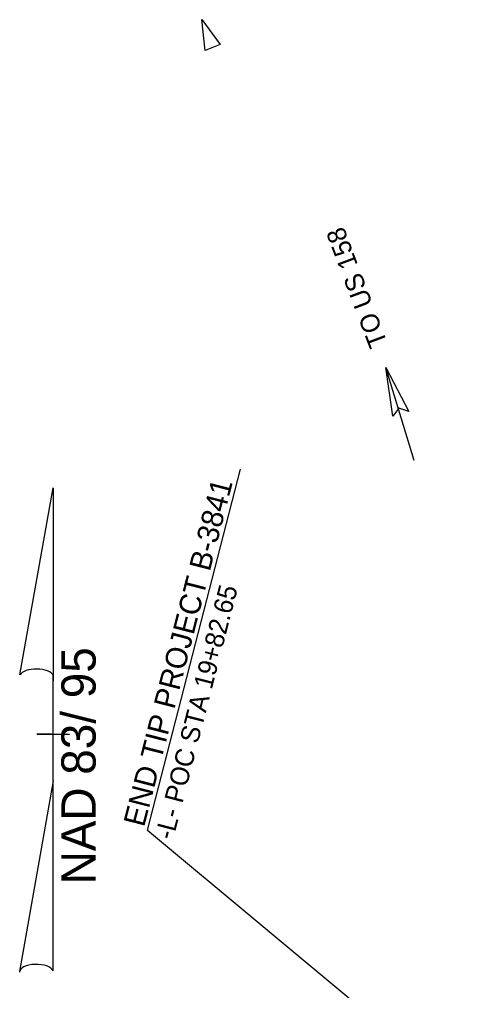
# Model space of a CAD drawing. Extents: x 2078889 to 2079501, y 925860 to 927219.
# Drawn here: x 2079231.9 to 2079401.1, y 926858.4 to 927219.4 of the extents above; entities that cross this region are included whole.
import ezdxf

# ---------------------------------------------------------------- set-up
doc = ezdxf.new("R2010")
doc.units = 0
for name, color, linetype in [('Default', 7, 'Continuous'), ('Prop Horizontal Alignment Curve and Spiral Data', 7, 'Continuous'), ('Prop Horizontal Alignment Direction Label', 7, 'Continuous'), ('Prop Horizontal Alignment Station Label', 7, 'Continuous'), ('Prop North Arrow NAD83 for Plan Sheets CELL', 7, 'Continuous'), ('Prop Terminator CELL', 7, 'Continuous')]:
    doc.layers.add(name, color=color, linetype=linetype)

msp = doc.modelspace()

# ---------------------------------------------------------------- linework, layer by layer
at = {"layer": 'Default'}
msp.add_lwpolyline([(2079300.92, 927207.92), (2079299.72, 927219.42), (2079306.51, 927210.06)], close=True, dxfattribs=at)
at = {"layer": 'Prop Horizontal Alignment Curve and Spiral Data'}
msp.add_line((2079279.57, 926918.1), (2079314.07, 927052.27), dxfattribs=at)
at = {"layer": 'Prop Horizontal Alignment Direction Label'}
msp.add_line((2079378.67, 927055.43), (2079368.16, 927090), dxfattribs=at)
at = {"layer": 'Prop Horizontal Alignment Station Label'}
msp.add_line((2079279.57, 926918.1), (2079401.11, 926816.87), dxfattribs=at)
at = {"layer": 'Prop North Arrow NAD83 for Plan Sheets CELL'}
for p, q in [((2079232.09, 926975.77), (2079244.41, 927045.29)), ((2079244.49, 927045.29), (2079244.41, 927045.29)), ((2079244.49, 927045.29), (2079244.41, 927045.29)), ((2079244.49, 927045.29), (2079244.47, 926973.59)), ((2079244.46, 926936.39), (2079244.47, 926975.69)), ((2079244.47, 926973.59), (2079244.47, 926975.62)), ((2079238.46, 926953.8), (2079238.39, 926953.8)), ((2079243.79, 926953.79), (2079238.46, 926953.8)), ((2079238.54, 926953.8), (2079250.54, 926953.79)), ((2079244.46, 926936.39), (2079231.91, 926865.52)), ((2079244.51, 926865.82), (2079244.46, 926936.39))]:
    msp.add_line(p, q, dxfattribs=at)
for centre, start_param, end_param in [((2079238.3, 926975.03), 0.216388, 2.908219), ((2079238.27, 926865.27), 0.201328, 3.141593)]:
    msp.add_ellipse(centre, major_axis=(6.34, -0.05), ratio=0.461098, start_param=start_param, end_param=end_param, dxfattribs=at)
at = {"layer": 'Prop Terminator CELL'}
msp.add_lwpolyline([(2079370.7, 927071.91), (2079368.18, 927090), (2079376.73, 927073.73), (2079372.99, 927074.95)], close=True, dxfattribs=at)

# ---------------------------------------------------------------- texts
at = {"layer": 'Default'}
msp.add_text('END TIP PROJECT B-3841', height=8, rotation=75.5809, dxfattribs=at).set_placement((2079278.24, 926918.95))
at = {"layer": 'Prop Horizontal Alignment Direction Label'}
msp.add_text('TO US 158', height=7, rotation=110.687, dxfattribs=at).set_placement((2079368.86, 927099.01))
at = {"layer": 'Prop Horizontal Alignment Station Label'}
msp.add_text('-L- POC STA 19+82.65', height=7, rotation=75.5809, dxfattribs=at).set_placement((2079288.99, 926914.14))
at = {"layer": 'Prop North Arrow NAD83 for Plan Sheets CELL'}
msp.add_text('NAD 83/ 95', height=12.75, rotation=89.9831, dxfattribs=at).set_placement((2079260.23, 926897.93))

doc.saveas('drawing.dxf')
